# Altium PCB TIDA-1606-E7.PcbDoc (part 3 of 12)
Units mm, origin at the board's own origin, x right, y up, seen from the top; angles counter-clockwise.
Board outline 270 x 345 mm, 4 copper layers (Top Layer, Signal Layer 1, Signal Layer 2, Bottom Layer), stack 2.326 mm thick; 1282 components, 576 nets, 3628 pads, 4132 vias.
Unrouted connection lines stored in the file: 1719.
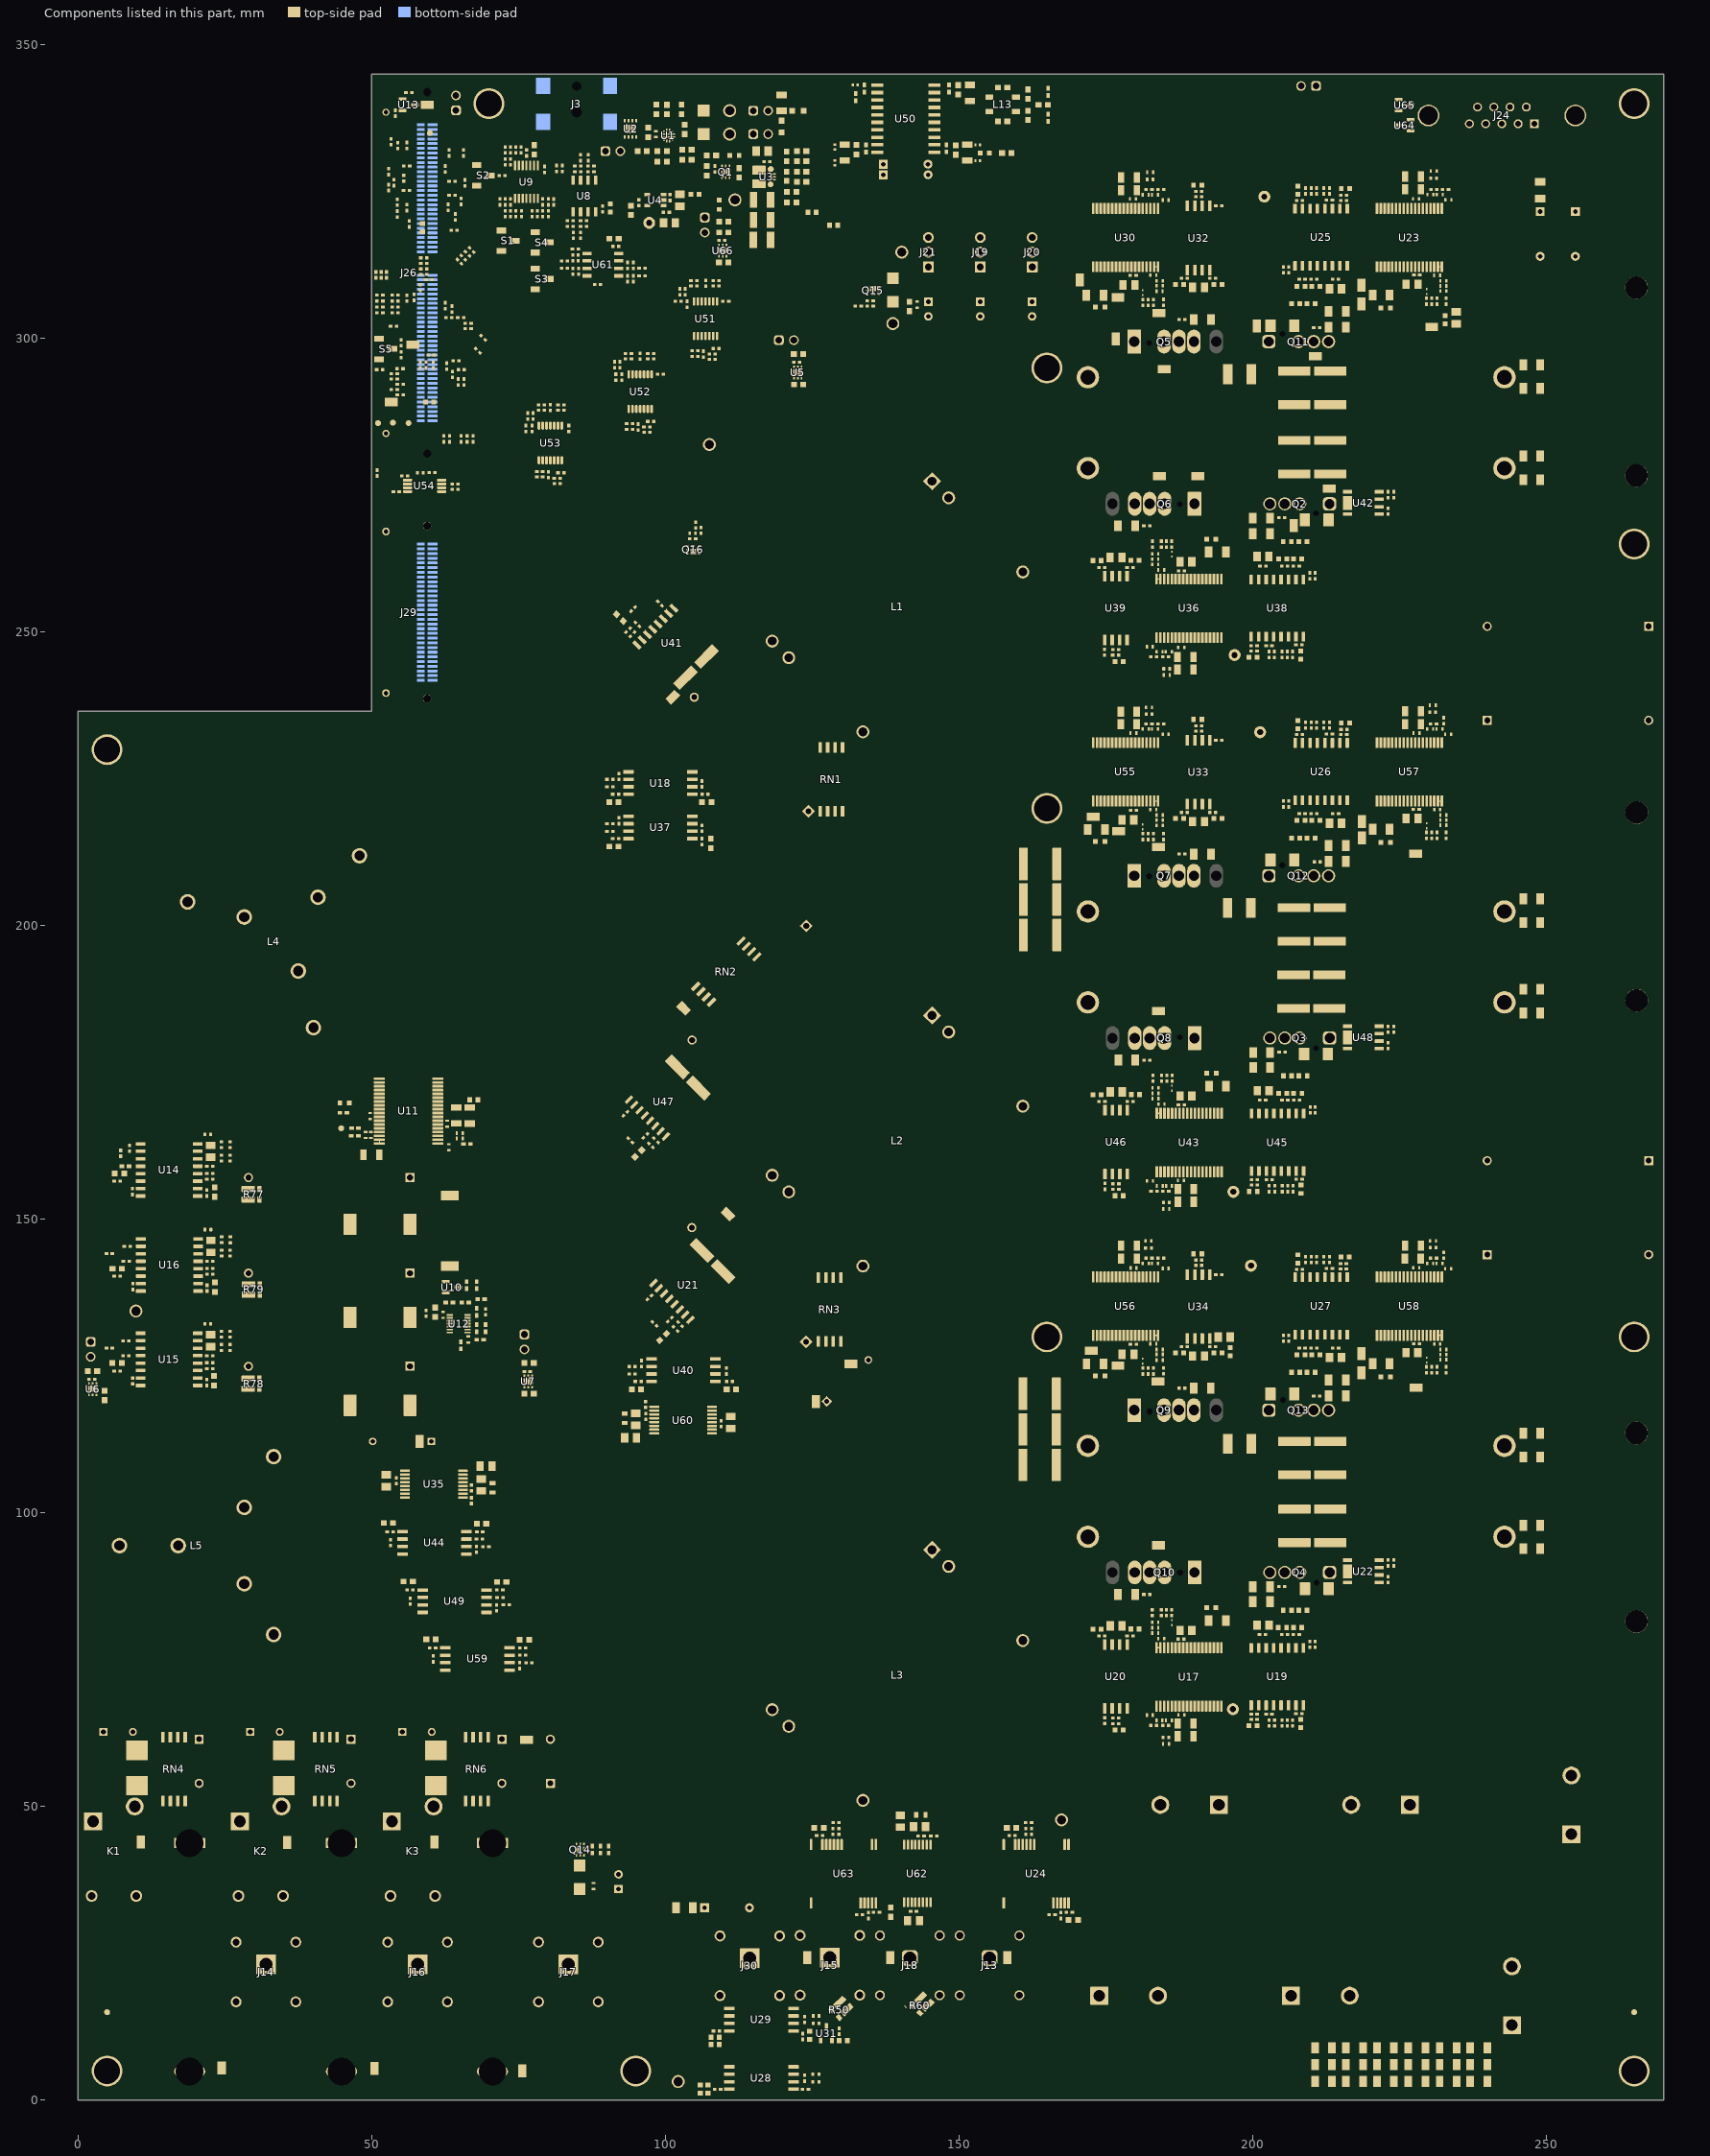
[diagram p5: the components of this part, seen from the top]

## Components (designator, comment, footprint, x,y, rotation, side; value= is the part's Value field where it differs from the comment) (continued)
R386 "RT0603DRE0759R7L" 0603 161.798,338 r90 top value=59.7
R387 "RCS06030000Z0EA" 0603 157.48,336.955 r180 top value=0
R388 "CRCW040210R0JNED" 0402L 102.246,306.331 r180 top value=10
R389 "CRCW040210K0FKED" 0402L 93.952,284.529 r0 top value=10.0k
R392 "CRCW040210K0FKED" 0402L 96.906,284.029 r180 top value=10.0k
R396 "RC0402JR-070RL" 0402L 65.702,331.592 r270 top value=0
R398 "CRCW040210K0FKED" 0402L 97.552,297.448 r180 top value=10.0k
R403 "CRCW040210K0FKED" 0402L 93.756,297.465 r0 top value=10.0k
R411 "RC0402JR-070RL" 0402L 52.902,325.704 r90 top value=0
R412 "CRCW040210R0JNED" 0402L 76.315,284.673 r270 top value=10
R413 "CRCW040210K0FKED" 0402L 76.602,286.8 r270 top value=10.0k
R414 "CRCW040210K0FKED" 0402L 78.662,276.42 r0 top value=10.0k
R415 "CRCW040210K0FKED" 0402L 81.637,275.288 r180 top value=10.0k
R422 "CRCW040210K0FKED" 0402L 82.262,288.707 r180 top value=10.0k
R424 "CRCW040210K0FKED" 0402L 78.937,288.707 r0 top value=10.0k
R433 "CRCW040210K0FKED" 0402L 106.123,267.335 r90 top value=10.0k
R434 "ERJ-2GEJ104X" 0402S 104.675,266.835 r180 top value=100k
R435 "RC0402JR-070RL" 0402L 60.202,297.185 r0 top value=0
R436 "CRCW040210K0FKED" 0402L 51.443,307.385 r180 top value=10.0k
R437 "RC0402JR-070RL" 0402L 62.602,305.6 r90 top value=0
R438 "CRCW040210K0FKED" 0402L 51.443,306.385 r180 top value=10.0k
R439 "CRCW040210K0FKED" 0402L 51.443,305.385 r180 top value=10.0k
R440 "CRCW040210K0FKED" 0402L 51.443,304.385 r180 top value=10.0k
R441 "CRCW040210K0FKED" 0402L 54.024,307.385 r180 top value=10.0k
R442 "CRCW040210K0FKED" 0402L 54.024,306.385 r180 top value=10.0k
R443 "CRCW040210K0FKED" 0402L 54.024,305.385 r180 top value=10.0k
R444 "CRCW040210K0FKED" 0402L 54.024,304.385 r180 top value=10.0k
R445 "RC0402JR-070RL" 0402L 65.202,303.6 r180 top value=0
R446 "RC0402JR-070RL" 0402L 232.881,325.405 r180 top value=0
R447 "RC0402JR-070RL" 0402L 184.422,325.368 r180 top value=0
R448 "RC0402JR-070RL" 0402L 183.201,245.798 r0 top value=0
R449 "RC0402JR-070RL" 0402L 53.75,302.1 r180 top value=0
R450 "RC0402JR-070RL" 0402L 183.242,154.832 r0 top value=0
R452 "RC0402JR-070RL" 0402L 52.562,310.839 r90 top value=0
R455 "CRCW0402200RJNED" 0402L 105.192,268.228 r270 top value=200
R457 "RC0402JR-070RL" 0402L 68.114,297.936 r135 top value=0
R458 "RC0402JR-070RL" 0402L 51.662,310.839 r90 top value=0
R459 "RC0402JR-070RL" 0402L 65.753,292.6 r90 top value=0
R460 "RC0402JR-070RL" 0402L 50.762,310.839 r90 top value=0
R461 "CRCW04023K30JNED" 0402L 64.237,274.348 r0 top value=3.3k
R462 "RC0402JR-070RL" 0402L 65.302,294.7 r180 top value=0
R463 "RC0402JR-070RL" 0402L 64.401,296.2 r180 top value=0
R464 "RC0402JR-070RL" 0402L 59.302,295.5 r270 top value=0
R465 "RC0402JR-070RL" 0402L 58.317,295.5 r270 top value=0
R466 "RC0402JR-070RL" 0402L 60.502,295.5 r90 top value=0
R467 "RC0402JR-070RL" 0402L 51.386,294.7 r180 top value=0
R469 "RC0402JR-070RL" 0402L 67.28,282.92 r90 top value=0
R470 "RC0402JR-070RL" 0402L 54.878,294.865 r0 top value=0
R471 "RC0402JR-070RL" 0402L 66.28,282.92 r90 top value=0
R472 "RC0402JR-070RL" 0402L 54.902,292.2 r0 top value=0
R475 "RC0402JR-070RL" 0402L 65.28,282.92 r90 top value=0
R476 "RC0402JR-070RL" 0402L 54.902,290.409 r0 top value=0
R477 "RC0402JR-070RL" 0402L 51.002,277.1 r90 top value=0
R478 "RC0402JR-070RL" 0402L 63.302,282.92 r90 top value=0
R481 "RC0402JR-070RL" 0402L 62.322,282.92 r90 top value=0
R505 "MCS0402MD1002BE100" 0402S 184.209,218.85 r180 top value=10.0k
R506 "PCF0402-03-49K9BT1" 0402S 184.209,217.104 r180 top value=49.9k
R507 "CRCW0402392RFKED" 0402L 181.328,306.146 r270 top value=392
R508 "ERJ-2GEJ104X" 0402S 185.225,141.635 r0 top value=100k
R509 "CRCW040230K0FKED" 0402L 182.399,143.405 r180 top value=30.0k
R510 "CRCW040266K5FKED" 0402L 184.868,306.163 r270 top value=66.5k
R511 "CRCW040230K0FKED" 0402L 183.156,306.146 r270 top value=30.0k
R512 "MCS0402MD1002BE100" 0402S 183.409,142.5 r180 top value=10.0k
R513 "MCS0402MD1002BE100" 0402S 184.209,127.855 r180 top value=10.0k
R514 "PCF0402-03-49K9BT1" 0402S 184.209,126.04 r180 top value=49.9k
R527 "CRCW04022K00FKED" 0402L 230.557,215.398 r90 top value=2.00k
R528 "ERJ-2GEJ104X" 0402S 233.317,232.6 r0 top value=100k
R529 "CRCW040230K0FKED" 0402L 230.84,234.4 r180 top value=30.0k
R530 "CRCW040266K5FKED" 0402L 184.87,215.194 r270 top value=66.5k
R531 "CRCW040230K0FKED" 0402L 183.158,215.178 r270 top value=30.0k
R532 "MCS0402MD1002BE100" 0402S 231.848,233.5 r180 top value=10.0k
R533 "MCS0402MD1002BE100" 0402S 232.506,218.834 r180 top value=10.0k
R534 "PCF0402-03-49K9BT1" 0402S 232.506,217.989 r180 top value=49.9k
R535 "ERJ-2RKF2490X" 0402L 229.666,215.398 r270 top value=249
R536 "ERJ-2GEJ104X" 0402S 233.317,141.605 r0 top value=100k
R537 "CRCW040230K0FKED" 0402L 230.84,143.405 r180 top value=30.0k
R538 "CRCW040266K5FKED" 0402L 184.87,124.199 r270 top value=66.5k
R539 "CRCW040230K0FKED" 0402L 183.158,124.182 r270 top value=30.0k
R540 "MCS0402MD1002BE100" 0402S 231.848,142.505 r180 top value=10.0k
R541 "MCS0402MD1002BE100" 0402S 232.506,127.839 r180 top value=10.0k
R542 "PCF0402-03-49K9BT1" 0402S 232.506,126.132 r180 top value=49.9k
R555 "CRCW04022K00FKED" 0402L 230.555,306.366 r90 top value=2.00k
R556 "CRCW04022K00FKED" 0402L 230.557,124.402 r90 top value=2.00k
R557 "ERJ-2RKF2490X" 0402L 229.666,124.402 r270 top value=249
R560 "CRCW12062K00JNEA" 1206 221.898,307.391 r180 top value=2.0k
R561 "CRCW12062K00JNEA" 1206 221.9,216.423 r180 top value=2.0k
R562 "CRCW12062K00JNEA" 1206 221.9,125.428 r180 top value=2.0k
R565 "CRCW0402392RFKED" 0402L 181.33,215.178 r270 top value=392
R566 "CRCW04022K00FKED" 0402L 182.244,124.182 r90 top value=2.00k
R567 "CRCW0402392RFKED" 0402L 181.33,124.182 r270 top value=392
R568 "CRCW12062K00JNEA" 1206 173.198,307.368 r180 top value=2.0k
R569 "CRCW12062K00JNEA" 1206 173.424,216.408 r180 top value=2.0k
R570 "CRCW12062K00JNEA" 1206 173.2,125.405 r180 top value=2.0k
RN1 "RES60A410QDWVRQ1" DWV0008A-MFG 128.305,224.928 r270 top
RN2 "RES60A410QDWVRQ1" DWV0008A-MFG 110.422,192.2 r45 top
RN3 "RES60A410QDWVRQ1" DWV0008A-MFG 128.005,134.65 r270 top
RN4 "RES60A410QDWVRQ1" DWV0008A-MFG 16.397,56.386 r90 top
RN5 "RES60A410QDWVRQ1" DWV0008A-MFG 42.262,56.386 r90 top
RN6 "RES60A410QDWVRQ1" DWV0008A-MFG 67.954,56.386 r90 top
S1 "CAS-120TA" SW_CAS-120TA 73.252,316.65 r0 top
S2 "CAS-120TA" SW_CAS-120TA 69.052,327.775 r0 top
S3 "CAS-120TA" SW_CAS-120TA 79.051,310.15 r0 top
S4 "CAS-120TA" SW_CAS-120TA 79.051,316.385 r0 top
S5 "CAS-120TA" SW_CAS-120TA 52.452,298.237 r0 top
TP1 "5010" Keystone5010 111.002,334.809 r0 top
TP2 "5011" Keystone5011 111.002,338.8 r0 top
TP3 "5010" Keystone5010 111.902,323.605 r90 top
TP4 "5011" Keystone5011 107.543,281.94 r90 top
TP5 "5000" Keystone5000 97.291,319.7 r90 top
TP6 "TP_SM_1MM" TP_SM_1MM 44.856,165.521 r240 top
TP7 "S2751-46R" Harwin_S2751-46R 58.166,112.196 r90 top
TP8 "5001" Keystone5001 196.676,66.6 r90 top
TP9 "S2751-46R" Harwin_S2751-46R 57.067,298.965 r180 top
TP10 "5011" Keystone5011 167.5,47.753 r0 top
TP11 "5001" Keystone5001 202.033,324.154 r90 top
TP12 "5011" Keystone5011 102.225,3.192 r0 top
TP13 "5011" Keystone5011 9.9,134.4 r0 top
TP14 "5001" Keystone5001 201.313,232.964 r90 top
TP15 "S2751-46R" Harwin_S2751-46R 53.402,289.185 r0 top
TP16 "TP_SM_1MM" TP_SM_1MM 51.118,285.6 r90 top
TP17 "5001" Keystone5001 196.754,154.7 r90 top
TP18 "TP_SM_1MM" TP_SM_1MM 53.651,285.662 r90 top
TP19 "TP_SM_1MM" TP_SM_1MM 56.318,285.6 r90 top
TP20 "5001" Keystone5001 196.971,246.1 r180 top
TP21 "S2751-46R" Harwin_S2751-46R 24.504,5.502 r90 top
TP22 "S2751-46R" Harwin_S2751-46R 10.733,44 r90 top
TP23 "5001" Keystone5001 199.755,142.12 r90 top
TP24 "S2751-46R" Harwin_S2751-46R 35.679,43.889 r90 top
TP25 "S2751-46R" Harwin_S2751-46R 50.548,5.416 r90 top
TP26 "S2751-46R" Harwin_S2751-46R 59.502,339.823 r0 top
TP27 "S2751-46R" Harwin_S2751-46R 75.692,5 r90 top
TP28 "S2751-46R" Harwin_S2751-46R 60.702,44 r90 top
TP29 "S2751-46R" Harwin_S2751-46R 213.081,274.472 r180 top
TP30 "S2751-46R" Harwin_S2751-46R 176.71,299.917 r270 top
TP31 "S2751-46R" Harwin_S2751-46R 190.678,276.53 r180 top
TP32 "S2751-46R" Harwin_S2751-46R 207.046,268.147 r90 top
TP33 "S2751-46R" Harwin_S2751-46R 184.963,294.792 r0 top
TP34 "S2751-46R" Harwin_S2751-46R 184.15,276.53 r0 top
TP35 "S2751-46R" Harwin_S2751-46R 101.313,238.923 r225 top
TP36 "S2751-46R" Harwin_S2751-46R 103.158,185.94 r315 top
TP37 "S2751-46R" Harwin_S2751-46R 110.698,150.898 r135 top
TP38 "S2751-46R" Harwin_S2751-46R 131.669,125.393 r180 top
TP39 "S2751-46R" Harwin_S2751-46R 125.691,119.001 r90 top
TP40 "S2751-46R" Harwin_S2751-46R 76.411,61.36 r180 top
TP41 "S2751-46R" Harwin_S2751-46R 218.592,305.914 r270 top
TP42 "S2751-46R" Harwin_S2751-46R 218.66,214.945 r90 top
TP43 "S2751-46R" Harwin_S2751-46R 230.528,301.985 r180 top
TP44 "S2751-46R" Harwin_S2751-46R 227.792,212.262 r180 top
TP45 "S2751-46R" Harwin_S2751-46R 218.583,309.1 r270 top
TP46 "S2751-46R" Harwin_S2751-46R 218.618,217.751 r270 top
TP47 "S2751-46R" Harwin_S2751-46R 218.548,123.905 r90 top
TP48 "S2751-46R" Harwin_S2751-46R 227.855,121.341 r180 top
TP49 "S2751-46R" Harwin_S2751-46R 218.592,127.178 r90 top
TP50 "S2751-46R" Harwin_S2751-46R 177.104,307 r180 top
TP51 "S2751-46R" Harwin_S2751-46R 177.261,216.104 r180 top
TP52 "S2751-46R" Harwin_S2751-46R 184.121,304.357 r0 top
TP53 "S2751-46R" Harwin_S2751-46R 184,213.439 r0 top
TP54 "S2751-46R" Harwin_S2751-46R 170.584,309.985 r90 top
TP55 "S2751-46R" Harwin_S2751-46R 172.878,218.54 r0 top
TP56 "S2751-46R" Harwin_S2751-46R 177.104,125.099 r180 top
TP57 "S2751-46R" Harwin_S2751-46R 183.9,122.412 r180 top
TP58 "S2751-46R" Harwin_S2751-46R 172.593,127.61 r180 top
TP59 "S2751-46R" Harwin_S2751-46R 200.721,302.157 r90 top
TP60 "S2751-46R" Harwin_S2751-46R 210.718,296.977 r0 top
TP61 "S2751-46R" Harwin_S2751-46R 183.998,185.504 r0 top
TP62 "S2751-46R" Harwin_S2751-46R 184.023,94.513 r0 top
TP63 "5010" Keystone5010 138.786,302.539 r0 top
TP64 "5011" Keystone5011 140.3,314.7 r0 top
TP65 "S2751-46R" Harwin_S2751-46R 158.242,24.308 r90 top
TP66 "S2751-46R" Harwin_S2751-46R 124.206,24.308 r90 top
TP67 "S2751-46R" Harwin_S2751-46R 138.354,24.308 r90 top
U1 "TPS259474LRPWT" RPW0010A-MFG 100.515,334.55 r90 top
U2 "TVS1401DRBR" DRB0008A 94.106,335.7 r90 top
U3 "TPSM863252RDXR" RDX0007A-MFG 116.669,327.528 r270 top
U4 "REF2033AIDDCR" DDC0005A_N 98.341,323.57 r180 top
U5 "TLV75533PDRVR" DRV0006A 122.588,294.218 r90 top
U6 "TLV75533PDRVR" DRV0006A 2.55,121.112 r90 top
U7 "TLV75533PDRVR" DRV0006A 76.69,122.401 r90 top
U8 "OPA2392DR" D0008A-MFG 86.252,324.254 r270 top
U9 "OPA4388IPWR" PW0014A-MFG 76.402,326.668 r270 top
U10 "TSM24CADBZR" DBZ0003A-MFG 63.699,138.451 r0 top
U11 "UCC14131QDWNRQ1" DWJ0036A-MFG 56.318,168.446 r180 top locked
U12 "TPSF12C3DYYR" DYY0014A-MFG 64.865,132.238 r0 top
U13 "TMP235A2DBZR" DBZ0003A-MFG 56.344,339.812 r0 top
U14 "AMC3306M05DWER" DWE0016A-MFG 15.566,158.425 r180 top
U15 "AMC3306M05DWER" DWE0016A-MFG 15.566,126.167 r180 top
U16 "AMC3306M05DWER" DWE0016A-MFG 15.608,142.24 r180 top
U17 "UCC14341BQDWNRQ1" DWN0036A-MFG 189.201,72.099 r90 top
U18 "AMC0330RDWVR" DWV0008A-MFG 99.2,224.304 r180 top
U19 "UCC21710QDWQ1" DW0016B_HV 204.245,72.136 r270 top
U20 "UCC5350MCDWVR" DWV0008A 176.764,72.165 r90 top
U21 "TMCS1123B2AQDVGR" DVG0010A-MFG 104.622,139.468 r225 top
U22 "ISOTMP35BEDFQRQ1" DFQ0007A-MFG 218.9,90.073 r180 top
U23 "UCC14341BQDWNRQ1" DWN0036A-MFG 226.732,317.19 r270 top
U24 "AMC0381D" DFX0015A-MFG 163.176,38.575 r90 top
U25 "UCC21710QDWQ1" DW0016B_HV 211.705,317.233 r90 top
U26 "UCC21710QDWQ1" DW0016B_HV 211.707,226.265 r90 top
U27 "UCC21710QDWQ1" DW0016B_HV 211.707,135.269 r90 top
U28 "AMC1302DWVR" DWV0008A 116.4,3.792 r180 top
U29 "AMC1302DWVR" DWV0008A 116.4,13.725 r180 top
U30 "UCC14341BQDWNRQ1" DWN0036A-MFG 178.403,317.19 r270 top
U31 "TLV76033DBZR" DBZ0003A_N 127.462,11.406 r90 top
U32 "UCC5350MCDWVR" DWV0008A 190.83,317.118 r270 top
U33 "UCC5350MCDWVR" DWV0008A 190.832,226.15 r270 top
U34 "UCC5350MCDWVR" DWV0008A 190.832,135.155 r270 top
U35 "UCC33421DHAR" DHA0016A-MFG 60.635,104.9 r180 top
U36 "UCC14341BQDWNRQ1" DWN0036A-MFG 189.199,254.06 r90 top
U37 "AMC0330RDWVR" DWV0008A-MFG 99.2,216.739 r180 top
U38 "UCC21710QDWQ1" DW0016B_HV 204.243,254.097 r270 top
U39 "UCC5350MCDWVR" DWV0008A 176.754,254.118 r90 top
U40 "AMC0330RDWVR" DWV0008A-MFG 103.143,124.317 r180 top
U41 "TMCS1123B2AQDVGR" DVG0010A-MFG 101.804,247.493 r135 top
U42 "ISOTMP35BEDFQRQ1" DFQ0007A-MFG 218.9,271.995 r180 top locked
U43 "UCC14341BQDWNRQ1" DWN0036A-MFG 189.241,163.094 r90 top
U44 "AMC0330RDWVR" DWV0008A-MFG 60.737,94.925 r0 top
U45 "UCC21710QDWQ1" DW0016B_HV 204.284,163.131 r270 top
U46 "UCC5350MCDWVR" DWV0008A 176.804,163.16 r90 top
U47 "TMCS1123B2AQDVGR" DVG0010A-MFG 100.436,170.71 r225 top
U48 "ISOTMP35BEDFQRQ1" DFQ0007A-MFG 218.9,180.994 r180 top locked
U49 "AMC0330RDWVR" DWV0008A-MFG 64.163,84.991 r0 top
U50 "ISOW1044DFM" DFM0020A-MFG 140.994,337.439 r0 top
U51 "SN74LVC126APWR" PW0014A_N 106.893,303.381 r90 top
U52 "SN74LVC126APWR" PW0014A_N 95.752,290.963 r90 top
U53 "SN74LVC126APWR" PW0014A_N 80.462,282.223 r90 top
U54 "LMK1C1103PWR" PW0008A-MFG 59.051,274.903 r180 top
U55 "UCC14341BQDWNRQ1" DWN0036A-MFG 178.405,226.222 r270 top
U56 "UCC14341BQDWNRQ1" DWN0036A-MFG 178.405,135.226 r270 top
U57 "UCC14341BQDWNRQ1" DWN0036A-MFG 226.734,226.222 r270 top
U58 "UCC14341BQDWNRQ1" DWN0036A-MFG 226.734,135.226 r270 top
U59 "AMC0330RDWVR" DWV0008A-MFG 68.047,75.151 r0 top
U60 "UCC33421DHAR" DHA0016A-MFG 103.075,115.825 r0 top
U61 "OPA2392DR" D0008A-MFG 89.402,312.589 r0 top
U62 "UCC33421DHAR" DHA0016A-MFG 142.952,38.63 r270 top
U63 "AMC0381D" DFX0015A-MFG 130.374,38.575 r90 top
U64 "TSM24CADBZR" DBZ0003A-MFG 225.922,336.315 r180 top
U65 "TSM24CADBZR" DBZ0003A-MFG 225.922,339.755 r0 top
U66 "TLV75533PDRVR" DRV0006A 109.817,314.983 r90 top
ZZ1 "This Assembly Note is for PCB labels only" AssemblyNoteLabel 170.282,-2.692 r0 top
ZZ2 "These assemblies are ESD sensitive, ESD precautions shall be observed." AssemblyNote 170.282,-5.471 r0 top
ZZ3 "These assemblies must be clean and free from flux and all contaminants. Use of no clean flux is not acceptable." AssemblyNote 170.281,-8.426 r0 top
ZZ4 "These assemblies must comply with workmanship standards IPC-A-610 Class 2, unless otherwise specified." AssemblyNote 170.28,-11.382 r0 top

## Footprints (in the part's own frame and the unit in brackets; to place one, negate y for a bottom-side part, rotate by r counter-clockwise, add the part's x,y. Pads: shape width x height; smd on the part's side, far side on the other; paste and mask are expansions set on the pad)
0402 [mm] "0402 from SM-752 data"
  rect 0.8x0.6 smd: 1(-0.6,0) 2(0.6,0)
  silkscreen extent -1.22,-0.52 1.22,0.52, body extent -0.55,-0.3 0.55,0.3, height 0.6
0402L [mm] "0402 from SM-752 data"
  rect 0.6x0.5 smd: 1(-0.5,0) 2(0.5,0)
  body extent -0.55,-0.3 0.55,0.3, height 0.6
0402S [mil] "Based on C0402S footprint from PADS legacy"
  rect 15x24 smd: 1(-20,0) 2(20,0)
  body extent -22,-12 22,12, height 24
0603 [mm] "0603 from SM-752 data"
  rect 1x0.95 smd: 1(-0.8,0) 2(0.8,0)
  silkscreen extent -1.52,-0.69 1.52,0.69, body extent -0.87,-0.47 0.87,0.47, height 1
0603L [mm] "0603 from SM-752 data"
  rect 0.8x0.85 smd: 1(-0.7,0) 2(0.7,0)
  silkscreen extent -0.07,-0.33 0.07,0.33, body extent -0.87,-0.47 0.87,0.47, height 1
0805_HV [mil] "0805 with 30mil clearance between pads"
  rect 50x63 smd: 1(-40,0) 2(40,0)
  silkscreen extent -74,-40 74,40, body extent -43,-29 43,29, height 57
1206 [mm] "1206 from SM-752 data"
  rect 1.3x1.85 smd: 1(-1.45,0) 2(1.45,0)
  silkscreen extent -2.4,-1.21 2.4,1.21, body extent -1.7,-0.9 1.7,0.9, height 1.35
1206_180L [mm] "1206_180"
  rect 1.1x1.75 smd: 1(-1.35,0) 2(1.35,0)
  silkscreen extent -0.4,-0.78 0.4,0.77, body extent -1.75,-0.95 1.75,0.95, height 1.8
1210_270 [mm] "1210"
  rect 1.3x2.7 smd: 1(-1.45,0) 2(1.45,0)
  silkscreen extent -2.32,-1.57 2.32,1.57, body extent -1.7,-1.35 1.7,1.35, height 2.7
1812_254 [mm] "SMD, 2-Leads, Body 4.8x3.4mm"
  rect 1.6x3.4 smd: 1(-2,0) 2(2,0)
  silkscreen extent -0.8,-1.7 0.8,1.7, body extent -2.4,-1.7 2.4,1.7, height 2.54
AssemblyNote [mm] "Assembly Note"
AssemblyNoteLabel [mm] "Assembly Note for PCB Labels"
CE_Mark_5mm [mm] "Minimum text height for CE Mark"
  silkscreen extent -3.5,-2.5 3.5,2.5
Cliff_FCR7350B [mm] "Panel Socket, R/A, TH"
  rrect50% 2.7x2.7 hole 2.2: 1(0,0)
  round 1.7 hole 1.2: 2(-5.08,3.8) 3(5.08,3.8) 4(5.08,-6.36) 5(-5.08,-6.36)
  silkscreen extent -6.01,-13.5 6.01,5.5, body extent -6,-27.5 6,5.5, height 12.3
Cliff_FCR7350R [mm] "Panel Socket, R/A, TH"
  rrect50% 2.7x2.7 hole 2.2: 1(0,0)
  round 1.7 hole 1.2: 2(-5.08,3.8) 3(5.08,3.8) 4(5.08,-6.36) 5(-5.08,-6.36)
  silkscreen extent -6.01,-13.5 6.01,5.5, body extent -6,-27.5 6,5.5, height 12.3
CPF0402 [mm] "TE Connectivity"
  rect 0.5x0.6 smd: 1(-0.5,0) 2(0.5,0)
  silkscreen extent -0.97,-0.53 0.97,0.53, body extent -0.55,-0.27 0.55,0.27, height 0.35
CUI_PJ-002AH-SMT [mm] "CUI"
  rect 2.8x2.4 smd: 1(-3.05,5.7) 1A(3.05,5.7) 2(-3.05,-5.7) 3(3.05,-5.7)
  round 1 hole 1.6 unplated: MH1(-3.05,0)
  round 1.524 hole 1.8 unplated: MH2(1.45,0)
  silkscreen extent -8.05,-4.5 6.75,5.45, body extent -8.05,-6.3 6.75,6.3, height 11.2
D0008A-MFG [mm]
  rrect17% 1.55x0.6 smd paste+0 mask+0: 1(-2.7,1.905) 2(-2.7,0.635) 3(-2.7,-0.635) 4(-2.7,-1.905) 5(2.7,-1.905) 6(2.7,-0.635) 7(2.7,0.635) 8(2.7,1.905)
  silkscreen extent -4.17,-2.5 1.5,2.5, body extent -3.57,-2.75 3.57,2.75, height 0.25
DBZ0003A-MFG [mm]
  rrect17% 1.3x0.6 smd paste+0 mask+0: 1(-1.05,0.95) 2(-1.05,-0.95) 3(1.05,0)
  silkscreen extent -0.7,-1.52 0.7,1.52, body extent -1.18,-1.46 1.19,1.46, height 1.12
DBZ0003A_N [mm] "SOT23, 3-Leads, Body 2.9x1.3mm, Pitch 0.95mm, Lead Span 2.4mm, IPC Medium Density"
  rrect17% 1x0.6 smd: 1(-1.2,0.95) 2(-1.2,-0.95) 3(1.2,0)
  silkscreen extent 0.2,-1.5 0.7,1.5, body extent -1.26,-1.46 1.26,1.46, height 0.98
DDC0005A_N [mm]
  rrect17% 1x0.6 smd: 1(-1.375,0.95) 2(-1.375,0) 3(-1.375,-0.95) 4(1.375,-0.95) 5(1.375,0.95)
  silkscreen extent -1.25,-1.52 0.88,1.57, body extent -1.41,-1.45 1.41,1.45, height 1.1
DFM0020A-MFG [mm]
  rrect17% 2.1x0.6 smd paste+0 mask+0: 1(-4.85,5.715) 2(-4.85,4.445) 3(-4.85,3.175) 4(-4.85,1.905) 5(-4.85,0.635) 6(-4.85,-0.635) 7(-4.85,-1.905) 8(-4.85,-3.175) 9(-4.85,-4.445) 10(-4.85,-5.715) 11(4.85,-5.715) 12(4.85,-4.445) 13(4.85,-3.175) 14(4.85,-1.905) 15(4.85,-0.635) 16(4.85,0.635) 17(4.85,1.905) 18(4.85,3.175) 19(4.85,4.445) 20(4.85,5.715)
  silkscreen extent -6.57,-6.47 3.4,6.47, body extent -6,-6.72 6,6.72, height 0.25
DFQ0007A-MFG [mm]
  rrect17% 1.55x0.6 smd paste+0 mask+0: 1(-2.7,1.905) 2(-2.7,0.635) 3(-2.7,-0.635) 4(-2.7,-1.905) 5(2.7,-1.905) 7(2.7,1.905)
  rrect6% 1.55x2.36 smd paste+0 mask+0: 6(2.7,0)
  silkscreen extent -4.14,-2.5 1.55,2.5, body extent -3.57,-2.75 3.57,2.75, height 0.25
DFX0015A-MFG [mm]
  rrect22% 1.85x0.45 smd paste+0 mask+0: 1(-4.975,5.525) 2(-4.975,-2.925) 3(-4.975,-3.575) 4(-4.975,-4.225) 5(-4.975,-4.875) 6(-4.975,-5.525) 7(4.975,-5.525) 8(4.975,-4.875) 9(4.975,0.325) 10(4.975,0.975) 11(4.975,1.625) 12(4.975,2.275) 13(4.975,2.925) 14(4.975,3.575) 15(4.975,5.525)
  silkscreen extent -6.57,-6.47 3.5,6.47, body extent -6,-6.72 6,6.72, height 0.25
DHA0016A-MFG [mm]
  rrect24% 1.65x0.41 smd paste+0 mask+0: 1(-4.925,2.275) 2(-4.925,1.625) 3(-4.925,0.975) 4(-4.925,0.325) 5(-4.925,-0.325) 6(-4.925,-0.975) 7(-4.925,-1.625) 8(-4.925,-2.275) 9(4.925,-2.275) 10(4.925,-1.625) 11(4.925,-0.975) 12(4.925,-0.325) 13(4.925,0.325) 14(4.925,0.975) 15(4.925,1.625) 16(4.925,2.275)
  silkscreen extent -6.43,-2.98 3.5,2.98, body extent -5.85,-3.22 5.85,3.22, height 0.25
DQK0006C [mm] "WSON"
  rrect12% 0.9x0.86 on Top Paste: 0(0,0.325)
  rrect34% 0.7x0.29 on Top Paste: 0(0.095,-0.65)
  rrect33% 0.45x0.3 smd: 1(-0.975,0.65) 2(-0.975,0) 3(-0.975,-0.65) 4(0.975,-0.65) 5(0.975,0) 6(0.975,0.65)
  rrect33% 0.75x0.3 smd paste-0.15: 7(0.095,-0.65)
  rrect11% 1x0.95 smd paste-0.5: 8(0,0.325)
  silkscreen extent -1.15,-1.15 1.15,1.15, body extent -1,-1 1,1, height 0.82
DRB0008A [mm] "VSON-8"
  rrect32% 0.6x0.31 smd: 1(-1.4,0.975) 2(-1.4,0.325) 3(-1.4,-0.325) 4(-1.4,-0.975) 5(1.4,-0.975) 6(1.4,-0.325) 7(1.4,0.325) 8(1.4,0.975)
  rrect7% 1.5x1.75 smd paste-0.75: 9(0,0)
  Top Layer region: -0.7,-0.875 -0.49,-0.875 -0.471,-0.879 -0.455,-0.89 -0.444,-0.906 -0.44,-0.925 -0.44,-0.925 -0.44,-1.65 -0.436,-1.669 -0.425,-1.685 -0.409,-1.696 -0.39,-1.7 -0.39,-1.7 -0.26,-1.7 -0.241,-1.696 -0.225,-1.685 -0.214,-1.669 -0.21,-1.65 -0.21,-1.65 -0.21,-0.925 -0.206,-0.906 -0.195,-0.89 -0.179,-0.879 -0.16,-0.875 -0.16,-0.875 0.16,-0.875 0.179,-0.879 0.195,-0.89 0.206,-0.906 0.21,-0.925 0.21,-0.925 0.21,-1.65 0.21,-1.65 0.214,-1.669 0.225,-1.685 0.241,-1.696 0.26,-1.7 0.26,-1.7 0.39,-1.7 0.409,-1.696 0.425,-1.685 0.436,-1.669 0.44,-1.65 0.44,-1.65 0.44,-0.925 0.444,-0.906 0.455,-0.89 0.471,-0.879 0.49,-0.875 0.49,-0.875 0.7,-0.875 0.719,-0.871 0.735,-0.86 0.746,-0.844 0.75,-0.825 0.75,-0.825 0.75,0.825 0.746,0.844 0.735,0.86 0.719,0.871 0.7,0.875 0.7,0.875 0.49,0.875 0.471,0.879 0.455,0.89 0.444,0.906 0.44,0.925 0.44,0.925 0.44,1.65 0.436,1.669 0.425,1.685 0.409,1.696 0.39,1.7 0.39,1.7 0.26,1.7 0.241,1.696 0.225,1.685 0.214,1.669 0.21,1.65 0.21,1.65 0.21,1.65 0.21,0.925 0.206,0.906 0.195,0.89 0.179,0.879 0.16,0.875 0.16,0.875 -0.16,0.875 -0.179,0.879 -0.195,0.89 -0.206,0.906 -0.21,0.925 -0.21,0.925 -0.21,1.65 -0.214,1.669 -0.225,1.685 -0.241,1.696 -0.26,1.7 -0.26,1.7 -0.39,1.7 -0.409,1.696 -0.425,1.685 -0.436,1.669 -0.44,1.65 -0.44,1.65 -0.44,0.925 -0.444,0.906 -0.455,0.89 -0.471,0.879 -0.49,0.875 -0.49,0.875 -0.7,0.875 -0.719,0.871 -0.735,0.86 -0.746,0.844 -0.75,0.825 -0.75,0.825 -0.75,-0.825 -0.746,-0.844 -0.735,-0.86 -0.719,-0.871 -0.7,-0.875
  silkscreen extent -1.73,-1.73 1.73,1.73, body extent -1.5,-1.5 1.5,1.5, height 0.77
DRV0006A [mm] "SON, 6-Leads, Body 2x2mm, Pitch 0.65mm, Thermal Pad 1.6x1mm, TI Recommended"
  rrect33% 0.45x0.3 smd: 1(-0.975,0.65) 2(-0.975,0) 3(-0.975,-0.65) 4(0.975,-0.65) 5(0.975,0) 6(0.975,0.65)
  rrect14% 1x0.7 on Top Paste: 7(0,0.45) 7(0,-0.45)
  rrect10% 1x1.6 smd paste-0.5: 7(0,0)
  silkscreen extent -1.05,-1.2 1.05,1.2, body extent -1.05,-1.05 1.05,1.05, height 0.81
DVG0010A-MFG [mm]
  rrect6% 1.65x4.41 smd paste+0 mask+0: 1(-4.875,2.54) 2(-4.875,-2.54)
  rrect17% 1.65x0.6 smd paste+0 mask+0: 3(4.875,-4.445) 4(4.875,-3.175) 5(4.875,-1.905) 6(4.875,-0.635) 7(4.875,0.635) 8(4.875,1.905) 9(4.875,3.175) 10(4.875,4.445)
  silkscreen extent -6.37,-5.25 3.67,5.25, body extent -5.8,-5.5 5.8,5.5, height 0.25
DW0016B_HV [mm] "SOIC-16, HV/isolation option"
  rrect17% 1.65x0.6 smd: 1(-4.875,4.445) 2(-4.875,3.175) 3(-4.875,1.905) 4(-4.875,0.635) 5(-4.875,-0.635) 6(-4.875,-1.905) 7(-4.875,-3.175) 8(-4.875,-4.445) 9(4.875,-4.445) 10(4.875,-3.175) 11(4.875,-1.905) 12(4.875,-0.635) 13(4.875,0.635) 14(4.875,1.905) 15(4.875,3.175) 16(4.875,4.445)
  body extent -5.17,-5.15 5.17,5.15, height 2.59
DWE0016A-MFG [mm]
  rrect17% 1.65x0.6 smd paste+0 mask+0: 1(-4.875,4.445) 2(-4.875,3.175) 3(-4.875,1.905) 4(-4.875,0.635) 5(-4.875,-0.635) 6(-4.875,-1.905) 7(-4.875,-3.175) 8(-4.875,-4.445) 9(4.875,-4.445) 10(4.875,-3.175) 11(4.875,-1.905) 12(4.875,-0.635) 13(4.875,0.635) 14(4.875,1.905) 15(4.875,3.175) 16(4.875,4.445)
  silkscreen extent -6.38,-5.25 3.5,5.25, body extent -5.8,-5.5 5.8,5.5, height 0.25
DWJ0036A-MFG [mm]
  rrect22% 1.85x0.45 smd paste+0 mask+0: 1(-4.975,5.525) 2(-4.975,4.875) 3(-4.975,4.225) 4(-4.975,3.575) 5(-4.975,2.925) 6(-4.975,2.275) 7(-4.975,1.625) 8(-4.975,0.975) 9(-4.975,0.325) 10(-4.975,-0.325) 11(-4.975,-0.975) 12(-4.975,-1.625) 13(-4.975,-2.275) 14(-4.975,-2.925) 15(-4.975,-3.575) 16(-4.975,-4.225) 17(-4.975,-4.875) 18(-4.975,-5.525) 19(4.975,-5.525) 20(4.975,-4.875) 21(4.975,-4.225) 22(4.975,-3.575) 23(4.975,-2.925) 24(4.975,-2.275) 25(4.975,-1.625) 26(4.975,-0.975) 27(4.975,-0.325) 28(4.975,0.325) 29(4.975,0.975) 30(4.975,1.625) 31(4.975,2.275) 32(4.975,2.925) 33(4.975,3.575) 34(4.975,4.225) 35(4.975,4.875) 36(4.975,5.525)
  silkscreen extent -6.57,-6.47 3.8,6.47, body extent -6,-6.72 6,6.71, height 0.25
DWN0036A-MFG [mm]
  rrect22% 1.85x0.45 smd paste+0 mask+0: 1(-4.975,5.525) 2(-4.975,4.875) 3(-4.975,4.225) 4(-4.975,3.575) 5(-4.975,2.925) 6(-4.975,2.275) 7(-4.975,1.625) 8(-4.975,0.975) 9(-4.975,0.325) 10(-4.975,-0.325) 11(-4.975,-0.975) 12(-4.975,-1.625) 13(-4.975,-2.275) 14(-4.975,-2.925) 15(-4.975,-3.575) 16(-4.975,-4.225) 17(-4.975,-4.875) 18(-4.975,-5.525) 19(4.975,-5.525) 20(4.975,-4.875) 21(4.975,-4.225) 22(4.975,-3.575) 23(4.975,-2.925) 24(4.975,-2.275) 25(4.975,-1.625) 26(4.975,-0.975) 27(4.975,-0.325) 28(4.975,0.325) 29(4.975,0.975) 30(4.975,1.625) 31(4.975,2.275) 32(4.975,2.925) 33(4.975,3.575) 34(4.975,4.225) 35(4.975,4.875) 36(4.975,5.525)
  silkscreen extent -6.57,-6.47 3.8,6.47, body extent -6,-6.72 6,6.72, height 0.25
DWV0008A [mm] "SOIC, 8-Leads, Body 5.95x7.6mm (max), Pitch 1.27mm"
  rrect17% 1.8x0.6 smd: 1(-5.45,1.905) 2(-5.45,0.635) 3(-5.45,-0.635) 4(-5.45,-1.905) 5(5.45,-1.905) 6(5.45,-0.635) 7(5.45,0.635) 8(5.45,1.905)
  silkscreen extent -6.25,-2.95 2.98,2.95, body extent -5.77,-2.92 5.77,2.93, height 2.67
DWV0008A-MFG [mm]
  rrect17% 1.8x0.6 smd paste+0 mask+0: 1(-5.45,1.905) 2(-5.45,0.635) 3(-5.45,-0.635) 4(-5.45,-1.905) 5(5.45,-1.905) 6(5.45,-0.635) 7(5.45,0.635) 8(5.45,1.905)
  silkscreen extent -7.1,-2.98 3.8,2.98, body extent -6.45,-3.22 6.45,3.23, height 0.25
DYY0014A-MFG [mm]
  rrect33% 1.05x0.3 smd paste+0 mask+0: 1(-1.5,1.5) 2(-1.5,1) 3(-1.5,0.5) 4(-1.5,0) 5(-1.5,-0.5) 6(-1.5,-1) 7(-1.5,-1.5) 8(1.5,-1.5) 9(1.5,-1) 10(1.5,-0.5) 11(1.5,0) 12(1.5,0.5) 13(1.5,1) 14(1.5,1.5)
  silkscreen extent -2.72,-2.15 1.05,2.15, body extent -1.63,-2.1 1.63,2.1, height 1.1
FCC_disclaimer [mm]
Fiducial10-20#1 [mm]
  round 1 smd mask+0.5: 1(0,0)
  Top Layer keep-out circle w1.178: c0,0 r0.5
Fiducial10-20#2 [mm]
  round 1 smd mask+0.5: 1(-0.05,0)
  Top Layer keep-out circle w1.178: c0,0 r0.5
FM_630x1120 [mm] "PANASONIC"
  rect 1.45x1.45 hole 0.787: 1(-1.25,0)
  round 1.45 hole 0.787: 2(1.25,0)
  silkscreen extent -3.4,-3.4 3.4,3.4, body extent -3.4,-3.4 3.41,3.4, height 12.71
FP-613_MNT_BRACKET-MFG [mm]
  round 3.88 hole 3.88 unplated paste-1000 mask+0: ""(0.985,0)
  silkscreen extent -5.08,-4.89 5.08,4.89, body extent -4.95,-4.76 4.95,4.76, height 11.76
FP-2071556-3_PTH_RELAY_18MM2_10MM2-MFG [mm]
  rrect3% 3.05x3.05 hole 2 paste-1000 mask+0: 1(-4.77,3.55)
  round 2 hole 1.3 paste-1000 mask+0: 2(7.93,3.8) 4(7.93,-3.8)
  round 3.05 hole 2 paste-1000 mask+0: 3(-7.31,-3.55)
  silkscreen extent -9.35,-5.35 9.35,6.02, body extent -9.1,-5.1 9.1,5.1, height 15.3
FP-0022111031_HDR3-MFG [mm]
  rrect5% 1.85x1.85 hole 1.2 paste-1000 mask+0: 1(2.5,0.3)
  round 1.85 hole 1.2 paste-1000 mask+0: 2(0,0.3) 3(-2.5,0.3)
  silkscreen extent -4.1,-3.1 4.7,3.1, body extent -3.5,-2.9 3.5,2.9, height 12.1
FP-9774040960R_ROUND_SPACER_6MM0-MFG [mm]
  round 5.245 smd paste-1000 mask-1000: 1(0,0)
  round 4.4 hole 4.4 unplated paste-1000 mask+0: ""(0,0)
  Top Layer circle w1.5: c0,0 r2.95
  silkscreen extent -4.1,-4.1 4.1,4.1, body extent -3.8,-3.8 3.8,3.8, height 0.25
FP-74269244182_0402-MFG [mm]
  rrect20% 0.5x0.6 smd paste+0 mask+0: 1(-0.5,0) 2(0.5,0)
  silkscreen extent -0.75,-0.67 0.75,0.67, body extent -0.85,-0.4 0.85,0.4, height 0.25
FP-ACT45B-101-2P-TL003_SMT_4MM5_3MM2-MFG [mm]
  rrect11% 1.35x0.9 smd paste+0 mask+0: 1(-2.275,1.25) 2(-2.275,-1.25) 3(2.275,-1.25) 4(2.275,1.25)
  silkscreen extent -3.62,-1.7 2.35,1.7, body extent -3.05,-1.8 3.05,1.8, height 0.25
FP-ALA8DA241CD500_RADIAL-MFG [mm]
  rrect3% 3.05x3.05 hole 2 paste-1000 mask+0: 1(-5,0)
  round 3.05 hole 2 paste-1000 mask+0: 2(5,0)
  silkscreen extent -15.5,-15.5 15.5,15.5, body extent -15,-15 15,15, height 42
FP-B32774H8395K000_RADIAL-MFG [mm]
  rrect6% 1.55x1.55 hole 1 paste-1000 mask+0: 1(-13.75,0)
  round 1.55 hole 1 paste-1000 mask+0: 2(13.75,0)
  silkscreen extent -15.75,-7 15.75,7, body extent -15.75,-7 15.75,7, height 24.5
FP-B58043E5254M052_2220-MFG [mm]
  rrect7% 1.5x5.5 smd paste+0 mask+0: 1(-2.85,0) 2(2.85,0)
  silkscreen extent -1.73,-2.7 1.73,2.7, body extent -3.7,-2.85 3.7,2.85, height 0.25
"FP-B181108 D6665 V2_PTH_IND_52MM5_59MM0-MFG" [mm]
  rrect5% 2.2x2.2 hole 1.5 paste-1000 mask+0: 1(-19.25,12.925)
  round 2.2 hole 1.5 paste-1000 mask+0: 2(-19.25,8.925) 3(-19.25,-8.925) 4(19.25,-8.925) 5(19.25,8.925) 6(19.25,12.925)
  silkscreen extent -26.97,-29.5 26.25,29.5, body extent -26.25,-29.5 26.25,29.5, height 41.6
FP-BLM15EX331SN1D_0402-MFG [mm]
  rrect25% 0.4x0.5 smd paste+0 mask+0: 1(-0.4,0) 2(0.4,0)
  silkscreen extent -0.53,-0.63 0.52,0.63, body extent -0.7,-0.38 0.7,0.38, height 0.25
FP-C3M0060065K_TO-247-4L-MFG [mm]
  rrect4% 4.06x2.29 hole 1.78 paste-1000 mask+0: 1(-0.212,5.08)
  rrect100% 4.06x2.29 hole 1.78 paste-1000 mask+0: 2(-0.212,0) 3(-0.212,-2.54) 4(-0.212,-5.08)
  silkscreen extent -3.13,-8.07 2.61,8.07, body extent -2.51,-7.97 2.51,7.97, height 27.97
FP-C247-075-3AE_PTH_HTSNK_75MM0_18MM0-MFG [mm]
  round 3.8 hole 2.5 paste-1000 mask+0: 1(-35.47,2.995) 2(35.47,2.995)
  silkscreen extent -37.5,-7.31 37.5,10.24, body extent -37.5,-9.71 37.5,10.23, height 38
FP-CSD17318Q2_WSON6-MFG [mm]
  rrect33% 0.45x0.3 smd paste+0 mask+0: 1(-0.975,0.65) 2(-0.975,0) 3(-0.975,-0.65) 4(0.975,-0.65) 5(0.975,0) 6(0.975,0.65)
  rrect33% 0.75x0.3 smd paste-1000 mask+0: 7(0.095,-0.65)
  rrect11% 1x0.95 smd paste-1000 mask+0: 8(0,0.325)
  body extent -1.3,-1.15 1.3,1.15, height 0.25
FP-DC0401012V2B_FAN-MFG [mm]
  body extent -5,-20 5,20, height 40
FP-DK1B3EA681K86RBH01_SMD2-MFG [mm]
  rrect5% 2.2x3.6 smd paste+0 mask+0: 1(-5.1,0) 2(5.1,0)
  silkscreen extent -4.25,-3.25 4.25,3.25, body extent -5.7,-3 5.7,3, height 2.5
FP-EVA86Q7UTF472KA01K_SMD2-MFG [mm]
  rrect6% 1.65x3 smd paste+0 mask+0: 1(-6.025,0) 2(6.025,0)
  silkscreen extent -4.25,-3.25 4.25,3.25, body extent -6.35,-3 6.35,3, height 4.2
FP-FCR7350G_CONN_BANANA_JACK-MFG [mm]
  rrect3% 3.35x3.35 hole 2.2 paste-1000 mask+0: 1(11,0)
  round 1.85 hole 1.2 paste-1000 mask+0: 2(4.64,5.08) 3(14.8,5.08) 4(4.64,-5.08) 5(14.8,-5.08)
  silkscreen extent -1.83,-6.05 17.2,6.05, body extent -16.5,-6 16.5,6, height 12.5
FP-FCR7350N_CONN_BANANA_JACK-MFG [mm]
  rrect3% 3.35x3.35 hole 2.2 paste-1000 mask+0: 1(11,0)
  round 1.85 hole 1.2 paste-1000 mask+0: 2(4.64,5.08) 3(14.8,5.08) 4(4.64,-5.08) 5(14.8,-5.08)
  silkscreen extent -1.83,-6.05 17.2,6.05, body extent -16.5,-6 16.5,6, height 12.5
FP-FCR7350Y_CONN_BANANA_JACK-MFG [mm]
  rrect3% 3.35x3.35 hole 2.2 paste-1000 mask+0: 1(11,0)
  round 1.85 hole 1.2 paste-1000 mask+0: 2(4.64,5.08) 3(14.8,5.08) 4(4.64,-5.08) 5(14.8,-5.08)
  silkscreen extent 5.94,-6 17.22,6, body extent -16.5,-6 16.5,6, height 12.5
FP-HSEC8-130-01-L-RA_HDR60-MFG [mm]
  rrect20% 0.5x1.35 smd paste+0 mask+0: 1(-11.6,2.2) 3(-10.8,2.2) 5(-10,2.2) 7(-9.2,2.2) 9(-8.4,2.2) 11(-7.6,2.2) 13(-6.8,2.2) 15(-6,2.2) 17(-5.2,2.2) 19(-4.4,2.2) 21(-3.6,2.2) 23(-2.8,2.2) 25(-2,2.2) 27(-1.2,2.2) 29(-0.4,2.2) 31(0.4,2.2) 33(1.2,2.2) 35(2,2.2) 37(2.8,2.2) 39(3.6,2.2) 41(4.4,2.2) 43(5.2,2.2) 45(6,2.2) 47(6.8,2.2) 49(7.6,2.2) 51(8.4,2.2) 53(9.2,2.2) 55(10,2.2) 57(10.8,2.2) 59(11.6,2.2)
  rrect20% 0.5x1.65 smd paste+0 mask+0: 2(-11.6,4.2) 4(-10.8,4.2) 6(-10,4.2) 8(-9.2,4.2) 10(-8.4,4.2) 12(-7.6,4.2) 14(-6.8,4.2) 16(-6,4.2) 18(-5.2,4.2) 20(-4.4,4.2) 22(-3.6,4.2) 24(-2.8,4.2) 26(-2,4.2) 28(-1.2,4.2) 30(-0.4,4.2) 32(0.4,4.2) 34(1.2,4.2) 36(2,4.2) 38(2.8,4.2) 40(3.6,4.2) 42(4.4,4.2) 44(5.2,4.2) 46(6,4.2) 48(6.8,4.2) 50(7.6,4.2) 52(8.4,4.2) 54(9.2,4.2) 56(10,4.2) 58(10.8,4.2) 60(11.6,4.2)
  round 1.31 hole 0.81 paste-1000 mask+0: 61(-13.75,-3.725) 62(13.75,-3.725)
  round 1.4 hole 1.4 unplated paste-1000 mask+0: ""(-14.7,3.275) ""(14.7,3.275)
  silkscreen extent -17.12,-4.9 16.36,6.09, body extent -16.3,-6.02 16.3,6.02, height 5.38
FP-IsoM5-275-B-L2_RADIAL-MFG [mm]
  rrect6% 1.55x1.55 hole 1 paste-1000 mask+0: 1(-3.75,0)
  round 1.55 hole 1 paste-1000 mask+0: 2(3.75,0)
  silkscreen extent -8.5,-3.15 8.5,3.15, body extent -8.5,-3.66 8.5,3.66, height 23
FP-LCMGA160808T601RG_0603-MFG [mm] "Recommended Land Pattern"
  rrect10% 1x1 smd paste+0 mask+0: 1(-1,0) 2(1,0)
  silkscreen extent -0.13,-0.45 0.13,0.45, body extent -1.6,-0.6 1.6,0.6, height 0.25
FP-PF-HT1-20_PTH_FUSE_38MM0_10MM3-MFG [mm]
  rrect6% 1.7x5.3 hole 4.7 slot 1.1 at 0 deg paste-1000 mask+0: 1(-19.45,0)
  rrect100% 1.7x5.3 hole 4.7 slot 1.1 at 0 deg paste-1000 mask+0: 2(19.45,0)
  silkscreen extent -19.3,-5.2 19.3,5.2, body extent -19.68,-5.15 19.68,5.15, height 12
FP-PTCEL13R600LBE_RADIAL-MFG [mm]
  rrect7% 1.35x1.35 hole 0.85 paste-1000 mask+0: 1(-2.5,0)
  round 1.35 hole 0.85 paste-1000 mask+0: 2(2.5,0)
  silkscreen extent -6.75,-3.5 6.75,3.5, body extent -6.75,-3.5 6.75,3.5, height 16.55
FP-R413F147050T1K_RADIAL-MFG [mm]
  rrect8% 1.3x1.3 hole 0.8 paste-1000 mask+0: 1(-5,0)
  round 1.3 hole 0.8 paste-1000 mask+0: 2(5,0)
  silkscreen extent -6.65,-2.6 6.65,2.6, body extent -6.5,-2.5 6.5,2.5, height 11.1
FP-R523R447050P1M_RADIAL-MFG [mm]
  rrect6% 1.55x1.55 hole 1 paste-1000 mask+0: 1(-13.75,0)
  round 1.55 hole 1 paste-1000 mask+0: 2(13.75,0)
  silkscreen extent -16.15,-7.1 16.15,7.1, body extent -16,-7 16,7, height 28.1
FP-UPR25J4R7CT_2512-MFG [mm]
  rrect3% 3.3x3.7 smd paste+0 mask+0: 1(-3,0) 2(3,0)
  silkscreen extent -0.97,-1.68 0.97,1.68, body extent -4.75,-1.95 4.75,1.95, height 0.25
FP-US1Q-TP_SMA-MFG [mm]
  rrect6% 1.78x2.16 smd paste+0 mask+0: 1(-2.025,0) 2(2.025,0)
  silkscreen extent -3.68,-1.46 2.37,1.46, body extent -3.02,-1.56 3.02,1.56, height 0.25
"FP-WK 3260A_PTH6_41MM5_43MM5-MFG" [mm]
  round 2.65 hole 1.75 paste-1000 mask+0: AI(0,7.5) AII(-6.5,-3.75) AIII(6.5,-3.75) EI(0,17.5) EII(-15.15,-8.75) EIII(15.15,-8.75)
  silkscreen extent -20.75,-21.73 20.75,22.7, body extent -20.75,-21.75 20.75,21.56, height 36.04
FP-WSKW06122L000FEA_0612-MFG [mm]
  rrect13% 1.01x0.762 smd paste+0 mask+0: E1(-0.885,1.334) E2(0.885,1.334)
  rrect10% 1.01x2.287 smd paste+0 mask+0: I1(-0.885,-0.571) I2(0.885,-0.571)
  silkscreen extent -2.07,-1.65 0,1.65, body extent -1.49,-1.81 1.49,1.81, height 0.25
Harwin_S2751-46R [mm] "Test Point, SMT"
  rect 2.2x1.4 smd: 1(0,0)
  body extent -1,-0.6 1,0.6, height 1.4
IEC_HighVoltage_Medium [mm]
  silkscreen extent -5.51,-4.46 5.51,5.09
IEC_HotSurface_Medium [mm]
  silkscreen extent -5.51,-4.76 5.51,4.78
Keystone5000 [mil] "For Keystone 500x miniature loop terminals"
  round 80 hole 40: 1(0,0)
  silkscreen extent -52,-52 52,52, body extent -49,-49 49,49, height 182
Keystone5001 [mil] "For Keystone 500x miniature loop terminals"
  round 80 hole 40: 1(0,0)
  silkscreen extent -52,-52 52,52, body extent -49,-49 49,49, height 182
Keystone5010 [mil] "Keystone Multipurpose loops"
  round 87 hole 63: 1(0,0)
  silkscreen extent -70,-70 70,70, body extent -63,-63 63,62, height 319
Keystone5011 [mil] "Keystone Multipurpose loops"
  round 87 hole 63: 1(0,0)
  silkscreen extent -70,-70 70,70, body extent -63,-63 63,62, height 319
Label_650x200 [mil] "Thermal Transfer Label"
  round 1 on Mech13: 0(0,0)
  silkscreen extent -325,-100 325,100, body extent -325,-100 325,100, height 1
Mill-Max_999-11-113-10-000000 [mil] "Shorting Jumper, 7.62mm, 2 Position, Gold, TH"
  rect 60x60 hole 30: 1(-150,0)
  round 60 hole 30: 2(150,0)
  silkscreen extent -102,-12 98,12, body extent -161,-11 161,11, height 105
Net-Tie7milsWide_20milsLong [mil] "7 mils wide by 20 mils long"
  rect 10x7 smd paste-5 mask-5: 1(-5,0) 2(5,0)
PW0008A-MFG [mm]
  rrect22% 1.5x0.45 smd paste+0 mask+0: 1(-2.9,0.975) 2(-2.9,0.325) 3(-2.9,-0.325) 4(-2.9,-0.975) 5(2.9,-0.975) 6(2.9,-0.325) 7(2.9,0.325) 8(2.9,0.975)
  silkscreen extent -4.33,-1.55 1.77,1.55, body extent -3.2,-1.5 3.2,1.5, height 1.2
PW0014A-MFG [mm]
  rrect29% 1.6x0.35 smd paste-1000 mask+0: 1(-2.8,1.95) 2(-2.8,1.3) 3(-2.8,0.65) 4(-2.8,0) 5(-2.8,-0.65) 6(-2.8,-1.3) 7(-2.8,-1.95) 8(2.8,-1.95) 9(2.8,-1.3) 10(2.8,-0.65) 11(2.8,0) 12(2.8,0.65) 13(2.8,1.3) 14(2.8,1.95)
  silkscreen extent -4.32,-2.55 2.25,2.55, body extent -3.7,-2.8 3.7,2.8, height 0.25
PW0014A_N [mm] "TSOP, 14-Leads, Body 5x4.4mm, Pitch 0.65mm, IPC Medium Density"
  oval 1.4x0.45 smd: 1(-2.95,1.95) 2(-2.95,1.3) 3(-2.95,0.65) 4(-2.95,0) 5(-2.95,-0.65) 6(-2.95,-1.3) 7(-2.95,-1.95) 8(2.95,-1.95) 9(2.95,-1.3) 10(2.95,-0.65) 11(2.95,0) 12(2.95,0.65) 13(2.95,1.3) 14(2.95,1.95)
  silkscreen extent -3.4,-2.55 1.85,2.55, body extent -3.21,-2.5 3.21,2.5, height 1
RDX0007A-MFG [mm]
  round 1.025 smd paste-1000 mask-1000: 1(-1.312,1.312)
  rrect13% 1.5x2.3 smd paste-1000 mask-1000: 2(-1.15,-0.675) 3(1.15,-0.675)
  round 0.991 smd paste-1000 mask-1000: 4(1.281,1.276)
  rrect45% 0.22x0.6 smd paste+0 mask-1000: 5(0.5,1.9) 6(0,1.9) 7(-0.5,1.9)
  Top Layer region: -1.9,1.8 -1.887,1.85 -1.85,1.887 -1.8,1.9 -1.8,1.9 -0.925,1.9 -0.887,1.892 -0.854,1.871 -0.833,1.838 -0.825,1.8 -0.825,1.8 -0.825,1.634 -0.818,1.596 -0.796,1.563 -0.796,1.563 -0.507,1.274 -0.474,1.252 -0.436,1.245 -0.436,1.245 -0.39,1.245 -0.34,1.232 -0.303,1.195 -0.29,1.145 -0.29,1.145 -0.29,0.825 -0.298,0.787 -0.319,0.754 -0.352,0.733 -0.39,0.725 -0.39,0.725 -1.8,0.725 -1.838,0.733 -1.871,0.754 -1.892,0.787 -1.9,0.825 -1.9,0.825
  Top Layer region: 1.9,1.8 1.892,1.838 1.871,1.871 1.838,1.892 1.8,1.9 1.8,1.9 0.925,1.9 0.887,1.892 0.854,1.871 0.833,1.838 0.825,1.8 0.825,1.8 0.825,1.634 0.818,1.596 0.796,1.563 0.796,1.563 0.507,1.274 0.474,1.252 0.436,1.245 0.436,1.245 0.39,1.245 0.352,1.237 0.319,1.216 0.298,1.183 0.29,1.145 0.29,1.145 0.29,0.825 0.298,0.787 0.319,0.754 0.352,0.733 0.39,0.725 0.39,0.725 1.8,0.725 1.838,0.733 1.871,0.754 1.892,0.787 1.9,0.825 1.9,0.825
  Top Layer keep-out region: -0.2,0.675 0.2,0.675 0.2,1.295 -0.2,1.295
  silkscreen extent -2.52,-2.17 2.07,2.37, body extent -2,-2.1 2,2.3, height 0.25
RPW0010A-MFG [mm]
  round 0.27 smd paste-1000 mask+0: 1(-0.75,0.7) 10(0.75,0.7)
  rrect40% 0.6x0.25 smd paste+0 mask+0: 2(-0.9,0.225) 3(-0.9,-0.225) 8(0.9,-0.225) 9(0.9,0.225)
  round 0.255 smd paste-1000 mask+0: 4(-0.75,-0.75) 7(0.75,-0.75)
  rrect33% 0.3x2.4 smd paste-1000 mask+0: 5(-0.25,0) 6(0.25,0)
  Top Layer region: 0.85,0.85 0.85,1.15 0.846,1.169 0.835,1.185 0.819,1.196 0.8,1.2 0.8,1.2 0.65,1.2 0.631,1.196 0.615,1.185 0.604,1.169 0.6,1.15 0.6,1.15 0.6,0.6 0.604,0.581 0.615,0.565 0.631,0.554 0.65,0.55 0.65,0.55 1.15,0.55 1.169,0.554 1.185,0.565 1.196,0.581 1.2,0.6 1.2,0.6 1.2,0.8 1.196,0.819 1.185,0.835 1.169,0.846 1.15,0.85 1.15,0.85
  Top Layer region: 0.85,-0.85 0.85,-1.15 0.846,-1.169 0.835,-1.185 0.819,-1.196 0.8,-1.2 0.8,-1.2 0.65,-1.2 0.631,-1.196 0.615,-1.185 0.604,-1.169 0.6,-1.15 0.6,-1.15 0.6,-0.6 0.604,-0.581 0.615,-0.565 0.631,-0.554 0.65,-0.55 0.65,-0.55 1.15,-0.55 1.169,-0.554 1.185,-0.565 1.196,-0.581 1.2,-0.6 1.2,-0.6 1.2,-0.8 1.196,-0.819 1.185,-0.835 1.169,-0.846 1.15,-0.85 1.15,-0.85
  Top Layer region: -0.85,-0.85 -0.85,-1.15 -0.846,-1.169 -0.835,-1.185 -0.819,-1.196 -0.8,-1.2 -0.8,-1.2 -0.65,-1.2 -0.631,-1.196 -0.615,-1.185 -0.604,-1.169 -0.6,-1.15 -0.6,-1.15 -0.6,-0.6 -0.604,-0.581 -0.615,-0.565 -0.631,-0.554 -0.65,-0.55 -0.65,-0.55 -1.15,-0.55 -1.169,-0.554 -1.185,-0.565 -1.196,-0.581 -1.2,-0.6 -1.2,-0.6 -1.2,-0.8 -1.196,-0.819 -1.185,-0.835 -1.169,-0.846 -1.15,-0.85 -1.15,-0.85
  Top Layer region: -0.85,0.85 -0.85,1.15 -0.843,1.175 -0.825,1.193 -0.8,1.2 -0.8,1.2 -0.65,1.2 -0.631,1.196 -0.615,1.185 -0.604,1.169 -0.6,1.15 -0.6,1.15 -0.6,0.6 -0.604,0.581 -0.615,0.565 -0.631,0.554 -0.65,0.55 -0.65,0.55 -1.15,0.55 -1.169,0.554 -1.185,0.565 -1.196,0.581 -1.2,0.6 -1.2,0.6 -1.2,0.8 -1.193,0.825 -1.175,0.843 -1.15,0.85 -1.15,0.85
  silkscreen extent -1.87,-1.58 1.05,1.58, body extent -1.3,-1.3 1.3,1.3, height 0.25
Samtec_HSEC8-160-01-x-RA-BL [mm] "Receptacle,  0.8mm, 60x2, SMT"
  rrect20% 1.35x0.5 smd mask+0.05: 1(-1.075,25.2) 3(-1.075,24.4) 5(-1.075,23.6) 7(-1.075,22.8) 9(-1.075,22) 11(-1.075,21.2) 13(-1.075,20.4) 15(-1.075,19.6) 17(-1.075,18.8) 19(-1.075,18) 21(-1.075,17.2) 23(-1.075,16.4) 25(-1.075,15.6) 27(-1.075,14.8) 29(-1.075,14) 31(-1.075,13.2) 33(-1.075,12.4) 35(-1.075,11.6) 37(-1.075,10.8) 39(-1.075,10) 41(-1.075,9.2) 43(-1.075,8.4) 45(-1.075,7.6) 47(-1.075,6.8) 49(-1.075,6) 51(-1.075,5.2) 53(-1.075,4.4) 55(-1.075,3.6) 57(-1.075,2.8) 59(-1.075,2) 61(-1.075,1.2) 63(-1.075,0.4) 65(-1.075,-3.6) 67(-1.075,-4.4) 69(-1.075,-5.2) 71(-1.075,-6) 73(-1.075,-6.8) 75(-1.075,-7.6) 77(-1.075,-8.4) 79(-1.075,-9.2) 81(-1.075,-10) 83(-1.075,-10.8) 85(-1.075,-11.6) 87(-1.075,-12.4) 89(-1.075,-13.2) 91(-1.075,-14) 93(-1.075,-14.8) 95(-1.075,-15.6) 97(-1.075,-16.4) 99(-1.075,-17.2) 101(-1.075,-18) 103(-1.075,-18.8) 105(-1.075,-19.6) 107(-1.075,-20.4) 109(-1.075,-21.2) 111(-1.075,-22) 113(-1.075,-22.8) 115(-1.075,-23.6) 117(-1.075,-24.4) 119(-1.075,-25.2)
  rrect20% 1.65x0.5 smd mask+0.05: 2(0.925,25.2) 4(0.925,24.4) 6(0.925,23.6) 8(0.925,22.8) 10(0.925,22) 12(0.925,21.2) 14(0.925,20.4) 16(0.925,19.6) 18(0.925,18.8) 20(0.925,18) 22(0.925,17.2) 24(0.925,16.4) 26(0.925,15.6) 28(0.925,14.8) 30(0.925,14) 32(0.925,13.2) 34(0.925,12.4) 36(0.925,11.6) 38(0.925,10.8) 40(0.925,10) 42(0.925,9.2) 44(0.925,8.4) 46(0.925,7.6) 48(0.925,6.8) 50(0.925,6) 52(0.925,5.2) 54(0.925,4.4) 56(0.925,3.6) 58(0.925,2.8) 60(0.925,2) 62(0.925,1.2) 64(0.925,0.4) 66(0.925,-3.6) 68(0.925,-4.4) 70(0.925,-5.2) 72(0.925,-6) 74(0.925,-6.8) 76(0.925,-7.6) 78(0.925,-8.4) 80(0.925,-9.2) 82(0.925,-10) 84(0.925,-10.8) 86(0.925,-11.6) 88(0.925,-12.4) 90(0.925,-13.2) 92(0.925,-14) 94(0.925,-14.8) 96(0.925,-15.6) 98(0.925,-16.4) 100(0.925,-17.2) 102(0.925,-18) 104(0.925,-18.8) 106(0.925,-19.6) 108(0.925,-20.4) 110(0.925,-21.2) 112(0.925,-22) 114(0.925,-22.8) 116(0.925,-23.6) 118(0.925,-24.4) 120(0.925,-25.2)
  round 1.1 hole 1.4 unplated mask+0.102: ALIGN1(0,30.775) ALIGN2(0,-30.775)
  round 1.215 hole 0.81: MH1(-7,27.35) MH2(-7,-27.35)
  body extent -12.9,-33.65 2.75,33.65, height 6.26
SMA [mm] "Molded Diode, 2-Leads, Body 4.3x2.6mm, IPC Medium Density, based on OnSemi component dimensions and land pattern"
  rect 2x2 smd: 1(-2,0) 2(2,0)
  silkscreen extent -3.66,-1.57 2.79,1.57, body extent -2.6,-1.3 2.6,1.3, height 2.42
SOD-923 [mm] "ON-SEMI"
  rect 0.36x0.25 smd: 1(-0.42,0) 2(0.42,0)
  silkscreen extent -1.02,-0.38 -0.76,0.38, body extent -0.45,-0.35 0.45,0.35, height 0.44
SW_CAS-120TA [mm] "COPAL ELECTRONICS"
  rect 1.6x1 smd: 1(-1.15,1.75) 2(1.15,0) 3(-1.15,-1.75)
  silkscreen extent -2,-2.85 1.4,2.93, body extent -1.4,-2.85 1.4,2.85, height 2.51
TO-247-4 [mm] "FM, 4-Leads, Body 15.94x5.02mm, Pitch 2.54mm"
  rrect50% 2.24x2.24 hole 1.7: 1(-5.08,0)
  round 2.24 hole 1.7: 2(0,0) 3(2.54,0) 4(5.08,0)
  silkscreen extent -8.07,-2.49 8.07,2.72, body extent -8.07,-2.49 8.07,2.72, height 27.97
TP_SM_1MM [mm] "1mm Test Point, SMT"
  round 1 smd paste-0.5: 1(0,0)
WE-PMI_0603_L1.6W0.8H0.8 [mm] "Power Multilayer Inductor, body 1.6x0.8mm"
  rect 0.7x1 smd: 1(-0.8,0) 2(0.8,0)
  body extent -0.8,-0.4 0.8,0.4, height 0.8
WEEE_Minimum [mm] "WEEElie bin"
  silkscreen extent -2.42,-4.38 2.52,2.65
WL-SMCW_GREEN [mm] "WURTH"
  rect 0.8x0.8 smd: 1(-0.8,0) 2(0.8,0)
  silkscreen extent -1.9,-0.8 1.2,0.8, body extent -0.85,-0.45 0.85,0.45, height 0.8
WURTH_61300211121 [mm] "Header, 2.54mm, 2x1, TH"
  rrect50% 1.65x1.65 hole 1.15: 1(-1.27,0)
  round 1.65 hole 1.15: 2(1.27,0)
  body extent -2.54,-1.27 2.54,1.27, height 8.54
Wurth_618009231121 [mm] "Receptacle, D-Sub, 9 Position, R/A, TH"
  rect 1.5x1.5 hole 1: 1(-10.92,5.54)
  round 1.5 hole 1: 2(-10.92,2.77) 3(-10.92,0) 4(-10.92,-2.77) 5(-10.92,-5.54) 6(-8.08,4.155) 7(-8.08,1.385) 8(-8.08,-1.385) 9(-8.08,-4.155)
  round 3.7 hole 3.2: 10(-9.5,12.5) 11(-9.5,-12.5)
  silkscreen extent -12.78,-15.4 -0.53,15.4, body extent -12.5,-15.4 6,15.4, height 12.5

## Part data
C1 C3 C440 C442: library part CMP-0007052-4, "CAP, CERM, 1 uF, 35 V, +/- 10%, X7R, 0603", Cap_Case=0603, Manufacturer=TDK, Supplier Part Number 1=445-7414-1-ND, TempCo=X7R, Tolerance_%=10%, Value1=Unknown, Value2=35V, ValueDisplayed=1uF
C2 C13 C87 C89 C94 C134 C138 C147 C150 C152 C160 C163 C174 C178 C187 C190 C192 C200 C203 C205 C213 C216 C218 C234 C235 C238 C247 C250 C254 C257 C261 C264 C278 C282 C291 C294 C296 C304 C307 C321 C325 C334 C337 C339 C347 C350 C369 C399 C400 C407 C408 C415 C416 C423 C424 C431 C432 C433 C434 C435 C436 C437 C438 C439: library part CMP-0006356-2, "CAP, CERM, 0.1 uF, 50 V, +/- 10%, X7R, AEC-Q200 Grade 1, 0402", Cap_Case=0402, Manufacturer=MuRata, Supplier Part Number 1=490-10672-1-ND, TempCo=X7R, Tolerance_%=10%, Value1=Unknown, Value2=50V, ValueDisplayed=0.1uF
C4: library part CMP-0007477-4, "CAP, CERM, 2700 pF, 100 V, +/- 10%, X7R, 0603", Cap_Case=0603, Manufacturer=MuRata, Supplier Part Number 1=490-1480-1-ND, TempCo=X7R, Tolerance_%=10%, Value1=Unknown, Value2=100V, ValueDisplayed=2700pF
C5: library part CMP-0006985-4, "CAP, CERM, 3300 pF, 50 V, +/- 10%, X7R, 0603", Cap_Case=0603, Manufacturer=Kemet, Supplier Part Number 1=399-5339-1-ND, TempCo=X7R, Tolerance_%=10%, Value1=Unknown, Value2=50V, ValueDisplayed=3300pF
C6 C15 C18 C20 C23 C26 C29 C30 C57 C58 C62 C64 C65 C92 C95 C96 C98 C103 C104 C107 C108 C109 C116 C117 C118 C125 C126 C127 C143 C155 C157 C158 C159 C166 C170 C171 C177 C180 C183 C195 C208 C210 C211 C220 C222 C226 C243 C267 C270 C271 C281 C283 C287 C299 C302 C303 C308 C312 C314 C315 C317 C318 C322 C327 C328 C330 C338 C351 C354 C355 C359 C373 C374 C383 C384 C385 C393 C394 C402 C410 C417 C418 C425 C426 C429 C430 C443 C450 C457 C469 C483: library part CMP-0006659-2, "CAP, CERM, 0.1 uF, 25 V, +/- 10%, X7R, 0402", Cap_Case=0402, Manufacturer=MuRata, Supplier Part Number 1=490-10698-1-ND, TempCo=X7R, Tolerance_%=10%, Value1=Unknown, Value2=25V, ValueDisplayed=0.1uF
C7 C88: library part CMP-0006692-2, "CAP, CERM, 4700 pF, 50 V, +/- 10%, X7R, 0402", Cap_Case=0402, Manufacturer=MuRata, Supplier Part Number 1=490-1308-1-ND, TempCo=X7R, Tolerance_%=10%, Value1=Unknown, Value2=50V, ValueDisplayed=4700pF
C8: library part CMP-0007255-4, "CAP, CERM, 22 pF, 100 V, +/- 5%, C0G/NP0, 0603", Cap_Case=0603, Manufacturer=MuRata, Supplier Part Number 1=490-1335-1-ND, TempCo=C0G/NP0, Tolerance_%=5%, Value1=Unknown, Value2=100V, ValueDisplayed=22pF
C9 C10: library part CMP-0009220-2, "CAP, CERM, 47 uF, 10 V, +/- 10%, X7R, 1210", Cap_Case=1210, Manufacturer=MuRata, Supplier Part Number 1=490-5312-1-ND, TempCo=X7R, Tolerance_%=10%, Value1=Unknown, Value2=10V, ValueDisplayed=47uF
C11: library part CMP-0009224-2, "CAP, CERM, 22 uF, 25 V, +/- 10%, X7R, 1210", Cap_Case=1210, Manufacturer=MuRata, Supplier Part Number 1=490-5313-1-ND, TempCo=X7R, Tolerance_%=10%, Value1=Unknown, Value2=25V, ValueDisplayed=22uF
C12 C16 C21: library part CMP-0085283-1, "CAP, CERM, 10 µF, 16 V,+/- 10%, X7R, 0805", Cap_Case=0805, Manufacturer="Taiyo Yuden", TempCo=X7R, Tolerance_%=10%, Value2=16V, ValueDisplayed=10µF
C14: library part CMP-0006853-4, "CAP, CERM, 0.01 uF, 16 V, +/- 10%, X7R, 0603", Cap_Case=0603, Manufacturer=Kemet, Supplier Part Number 1=399-7841-1-ND, TempCo=X7R, Tolerance_%=10%, Value1=Unknown, Value2=16V, ValueDisplayed=0.01uF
